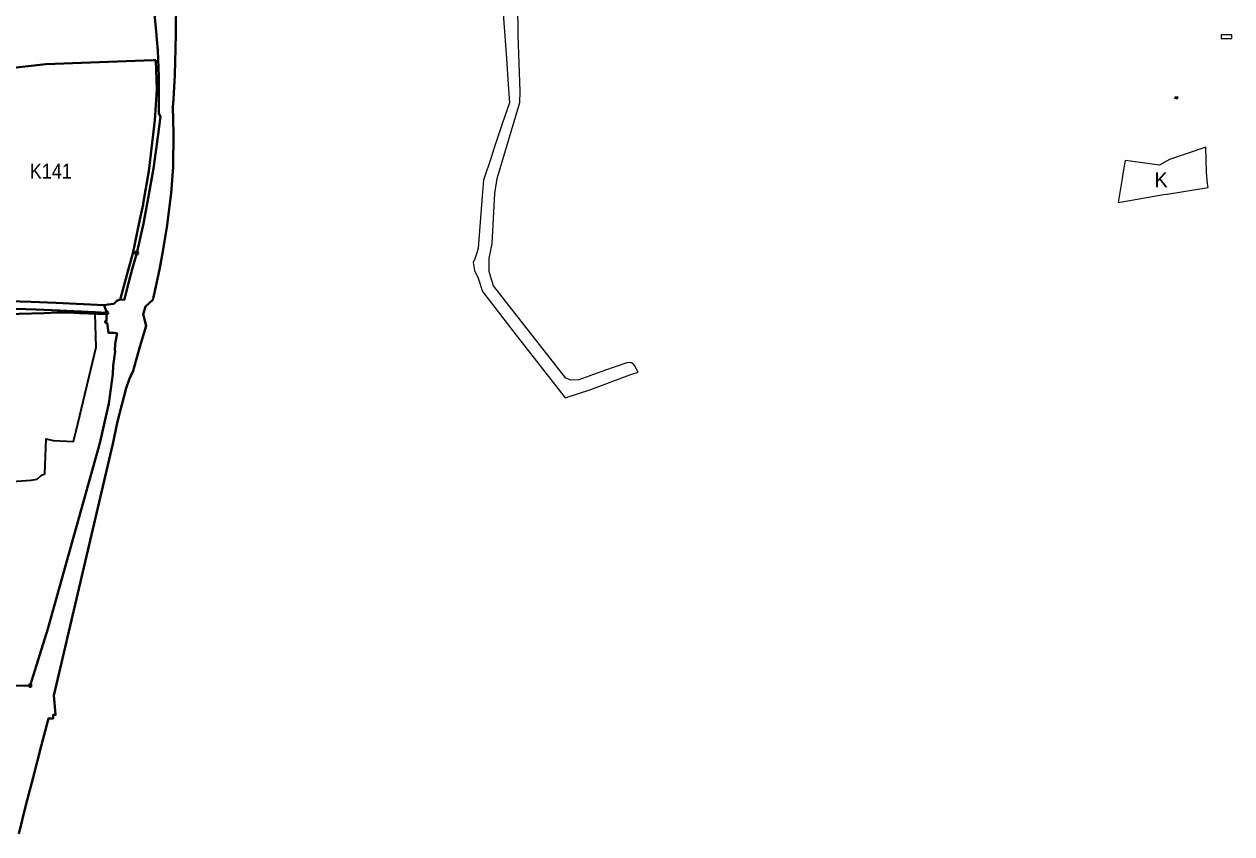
# Model space of a CAD drawing. Extents: x -650276 to -642489, y -1074425 to -1066658.
# Drawn here: x -645214 to -643276, y -1071606 to -1070307 of the extents above; entities that cross this region are included whole.
import ezdxf

# ---------------------------------------------------------------- set-up
doc = ezdxf.new("R2010")
doc.units = 0
doc.header["$LTSCALE"] = 9.6
doc.header["$PDMODE"] = 32
doc.header["$PDSIZE"] = 4.8
for name, color, linetype, lineweight in [('1', 7, 'Continuous', 13), ('43', 7, 'Continuous', 13), ('44', 7, 'Continuous', 40), ('47', 7, 'Continuous', 13), ('5', 7, 'Continuous', 35)]:
    doc.layers.add(name, color=color, linetype=linetype, lineweight=lineweight)

msp = doc.modelspace()

# ---------------------------------------------------------------- hatches: boundary and pattern name
at = {"layer": '1'}
msp.add_hatch(color=256, dxfattribs=at).paths.add_polyline_path([(-643366.86, -1070423.42), (-643363.11, -1070424.15), (-643363.78, -1070427.56), (-643367.55, -1070426.79)])

# ---------------------------------------------------------------- linework, layer by layer
for points in [[(-643281.55, -1070324.801), (-643283.69, -1070324.81), (-643293.29, -1070324.84), (-643293.27, -1070330.45), (-643285.64, -1070330.42)], [(-643285.64, -1070330.42), (-643276.25, -1070330.39), (-643276.27, -1070324.78), (-643281.55, -1070324.801)]]:
    msp.add_lwpolyline(points, dxfattribs=at)
msp.add_lwpolyline([(-643366.86, -1070423.42), (-643363.11, -1070424.15), (-643363.78, -1070427.56), (-643367.55, -1070426.79)], close=True, dxfattribs=at)
at = {"layer": '44'}
for points in [[(-645166.34, -1071384.07), (-645071.99, -1070980.72), (-645064.39, -1070944.7), (-645050.47, -1070891.48), (-645045.74, -1070877.19), (-645043, -1070871.35), (-645039.25, -1070863.33), (-645028.25, -1070824.83), (-645018.18, -1070791.34), (-645023.25, -1070772.62), (-645019.57, -1070760.07), (-645007.68, -1070749.5), (-645006.739, -1070745.384), (-645001.71, -1070723.39), (-644997.14, -1070700.88), (-644992.6, -1070677.92), (-644985.04, -1070633.43), (-644978.44, -1070578.56), (-644975.05, -1070536.16), (-644974.44, -1070482.48), (-644975.29, -1070440.14), (-644974.69, -1070427.86), (-644972.48, -1070389.15), (-644971.37, -1070345.98), (-644970.61, -1070323.44), (-644970.55, -1070321.56), (-644970.524, -1070315.358), (-644970.36, -1070275.49)], [(-645005.98, -1070280.14), (-645002.308, -1070319.268), (-645001.81, -1070324.58), (-645001.64, -1070326.4)], [(-645001.64, -1070326.4), (-644999.47, -1070349.63), (-644997.87, -1070391.16), (-644998.25, -1070430.5), (-644998.17, -1070450.59), (-644995.14, -1070455.72), (-644998.92, -1070484.58), (-645006.44, -1070538.78), (-645014.07, -1070580.72), (-645022.64, -1070626.93), (-645033.53, -1070674.55)], [(-645033.53, -1070674.55), (-645041, -1070700.44), (-645046.63, -1070722.77), (-645052.4, -1070746.427), (-645053.21, -1070749.75), (-645060.46, -1070749.1), (-645065.17, -1070751.39), (-645070.3, -1070755.92), (-645079.38, -1070756.91), (-645085.58, -1070758.04), (-645081.6, -1070770.362)], [(-645081.6, -1070770.362), (-645081.75, -1070772.79), (-645081.85, -1070781.59), (-645081.57, -1070783.53), (-645083.95, -1070783.89), (-645083.49, -1070786.92), (-645081.13, -1070786.56), (-645078.85, -1070802.46), (-645070.2, -1070802.33), (-645065.01, -1070803.22), (-645068.07, -1070820.37)], [(-645068.07, -1070820.37), (-645068.52, -1070830.52), (-645068.07, -1070832.72), (-645071.18, -1070855.63), (-645071.77, -1070868.73), (-645078.23, -1070915.65)], [(-645078.23, -1070915.65), (-645092.67, -1070979.52), (-645176.14, -1071277.26), (-645204.341, -1071368.19)], [(-645204.341, -1071368.19), (-645348.55, -1071370.559), (-645369.67, -1071368.678)], [(-645222.48, -1071606.08), (-645211.27, -1071560.01), (-645199.61, -1071515.68), (-645186.67, -1071465.55), (-645175.06, -1071420.93), (-645167.58, -1071421.19), (-645167.37, -1071415.2), (-645163.56, -1071415.3), (-645164.76, -1071401.79), (-645166.34, -1071384.07)]]:
    msp.add_lwpolyline(points, dxfattribs=at)
msp.add_lwpolyline([(-645275.8, -1070762.66), (-645195.527, -1070765.319), (-645156.988, -1070766.884), (-645100.32, -1070769.5), (-645081.6, -1070770.362), (-645081.75, -1070772.79), (-645125.217, -1070770.81), (-645143, -1070770), (-645161, -1070770), (-645182, -1070771), (-645303, -1070774), (-645351, -1070800), (-645400.05, -1070819.84), (-645385.99, -1070810.35), (-645342.94, -1070779.31), (-645333.12, -1070773.33), (-645321.9, -1070768.47), (-645309.78, -1070764.88), (-645296.51, -1070762.52)], close=True, dxfattribs=at)
for p in [(-645033.53, -1070674.55), (-645081.6, -1070770.362), (-645204.341, -1071368.19)]:
    msp.add_point(p, dxfattribs=at)
at = {"layer": '47'}
for points in [[(-644243.15, -1070849.89), (-644246.93, -1070850.52), (-644282.77, -1070863.19), (-644324.34, -1070877.71), (-644337.15, -1070878.64), (-644344.86, -1070875.09), (-644460.82, -1070727.21), (-644465.31, -1070713.25), (-644468.1, -1070704.23), (-644467.84, -1070682.37), (-644466.998, -1070678.065), (-644463.28, -1070659.06), (-644458.85, -1070579.04), (-644455.2, -1070554.88), (-644418.69, -1070433.36), (-644418.23, -1070415.62), (-644421.45, -1070325.29), (-644422.5, -1070226.42), (-644420.14, -1070208.56), (-644418.61, -1070204.51), (-644417.36, -1070203.24), (-644407.55, -1070194.16), (-644399.15, -1070188.55)], [(-644445.28, -1070290.84), (-644440.36, -1070362.62), (-644437.53, -1070404.1), (-644435.51, -1070433.85), (-644447.14, -1070467.28), (-644460.5, -1070507.68), (-644464.98, -1070521.13), (-644476.94, -1070557.45), (-644479.06, -1070583.13), (-644485.64, -1070666.7), (-644488.01, -1070674.2), (-644491.691, -1070685.524), (-644491.82, -1070685.92), (-644493.5, -1070689.75), (-644491.42, -1070702.64), (-644485.61, -1070714.95), (-644478.67, -1070736.28), (-644424.37, -1070806.03), (-644346.21, -1070906.61), (-644305.07, -1070893.39), (-644242.29, -1070869.82), (-644229.12, -1070865.52), (-644234.66, -1070855.08), (-644236.3, -1070852.87), (-644239.47, -1070850.71), (-644243.15, -1070849.89)], [(-643452.22, -1070592.35), (-643385.72, -1070580.86), (-643380.35, -1070580.14), (-643380.08, -1070580.09), (-643314.51, -1070569.69), (-643315.27, -1070563.2), (-643317.08, -1070544.75), (-643317.9, -1070504.73)], [(-643317.9, -1070504.73), (-643376.07, -1070524.59), (-643392.41, -1070533.68), (-643446.89, -1070526.01)], [(-643446.89, -1070526.01), (-643447.79, -1070528.63), (-643450.98, -1070547.74), (-643452.14, -1070554.77)], [(-643452.14, -1070554.77), (-643458.42, -1070593.43), (-643452.22, -1070592.35)]]:
    msp.add_lwpolyline(points, dxfattribs=at)
at = {"layer": '5', "lineweight": 40}
for points in [[(-645442.834, -1070659.455), (-645449.82, -1070592.72), (-645448.36, -1070563), (-645454.02, -1070501.52), (-645458.46, -1070478.86), (-645455.09, -1070479.21), (-645451.226, -1070466.394), (-645440.61, -1070469.53), (-645404.4, -1070435.88), (-645404.34, -1070433.93), (-645408.66, -1070414.62), (-645409.38, -1070411.41), (-645414.65, -1070395.37), (-645326.62, -1070388.32), (-645179.26, -1070371.74), (-645006.86, -1070365.38), (-645003.102, -1070365.432), (-645003.03, -1070365.427), (-645001.312, -1070412.099), (-645004.327, -1070461.264), (-645014.277, -1070543.11), (-645023.048, -1070595.033), (-645023.346, -1070596.478)], [(-645023.346, -1070596.478), (-645028.384, -1070620.876), (-645039.574, -1070675.065), (-645045.493, -1070696.321), (-645059.308, -1070747.712), (-645059.421, -1070749.039), (-645060.46, -1070749.1), (-645065.17, -1070751.39), (-645070.3, -1070755.92)], [(-645070.3, -1070755.92), (-645079.38, -1070756.91), (-645085.58, -1070758.04), (-645163.06, -1070754.64), (-645202.96, -1070752.89), (-645275.236, -1070750.954)]]:
    msp.add_lwpolyline(points, dxfattribs=at)
at = {"layer": '5'}
for points in [[(-645100.268, -1070771.946), (-645143, -1070770), (-645161, -1070770), (-645182, -1070771), (-645303, -1070774), (-645351, -1070800), (-645400.05, -1070819.84), (-645406.09, -1070822.34), (-645409.52, -1070823.76), (-645418.67, -1070827.72), (-645421.09, -1070827.89), (-645433.49, -1070828.76), (-645452.31, -1070825.52), (-645455.184, -1070825.042)], [(-645130.749, -1070959.561), (-645098.438, -1070825.558), (-645100.268, -1070771.946)], [(-645495.87, -1071017.81), (-645475.01, -1071020.72), (-645426.38, -1071032.8), (-645361.54, -1071041.54), (-645255.93, -1071042.36), (-645203.66, -1071038.81), (-645193.24, -1071037.31), (-645186.18, -1071030.83), (-645180.72, -1071028.86), (-645178.73, -1070972.35), (-645167.47, -1070975.2), (-645134.973, -1070977.077), (-645134.973, -1070977.077), (-645130.749, -1070959.561)]]:
    msp.add_lwpolyline(points, dxfattribs=at)

# ---------------------------------------------------------------- texts
at = {"layer": '43', "width": 0.9}
msp.add_text('K141', height=24, dxfattribs=at).set_placement((-645205.123, -1070555.263))
at = {"layer": '43'}
msp.add_text('K', height=24, dxfattribs=at).set_placement((-643400.597, -1070568.968))
msp.add_text('K', height=24, dxfattribs=at).set_placement((-643400.597, -1070568.968))

doc.saveas('drawing.dxf')
